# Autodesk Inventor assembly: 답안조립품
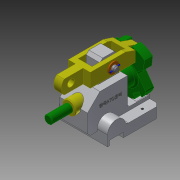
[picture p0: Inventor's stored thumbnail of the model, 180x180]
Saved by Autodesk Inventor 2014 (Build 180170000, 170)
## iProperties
Created: 2016-11
Part Number: 답안조립품
Document SubType Name: Assembly
Designer: USER
Author: USER
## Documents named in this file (8)
- C:\Users\USER\Desktop\461107V1025\답안조립품.iam
- C:\Users\USER\Desktop\461107V1025\본체.ipt
- C:\Users\USER\Desktop\461107V1025\부시.ipt
- C:\Users\USER\Desktop\461107V1025\분할대.ipt
- C:\Users\USER\Desktop\461107V1025\분할축.ipt
- C:\Users\USER\Desktop\461107V1025\와셔.ipt
- C:\Users\USER\Desktop\461107V1025\원통형핀.ipt
- C:\Users\USER\Desktop\461107V1025\클레비스핀.ipt
